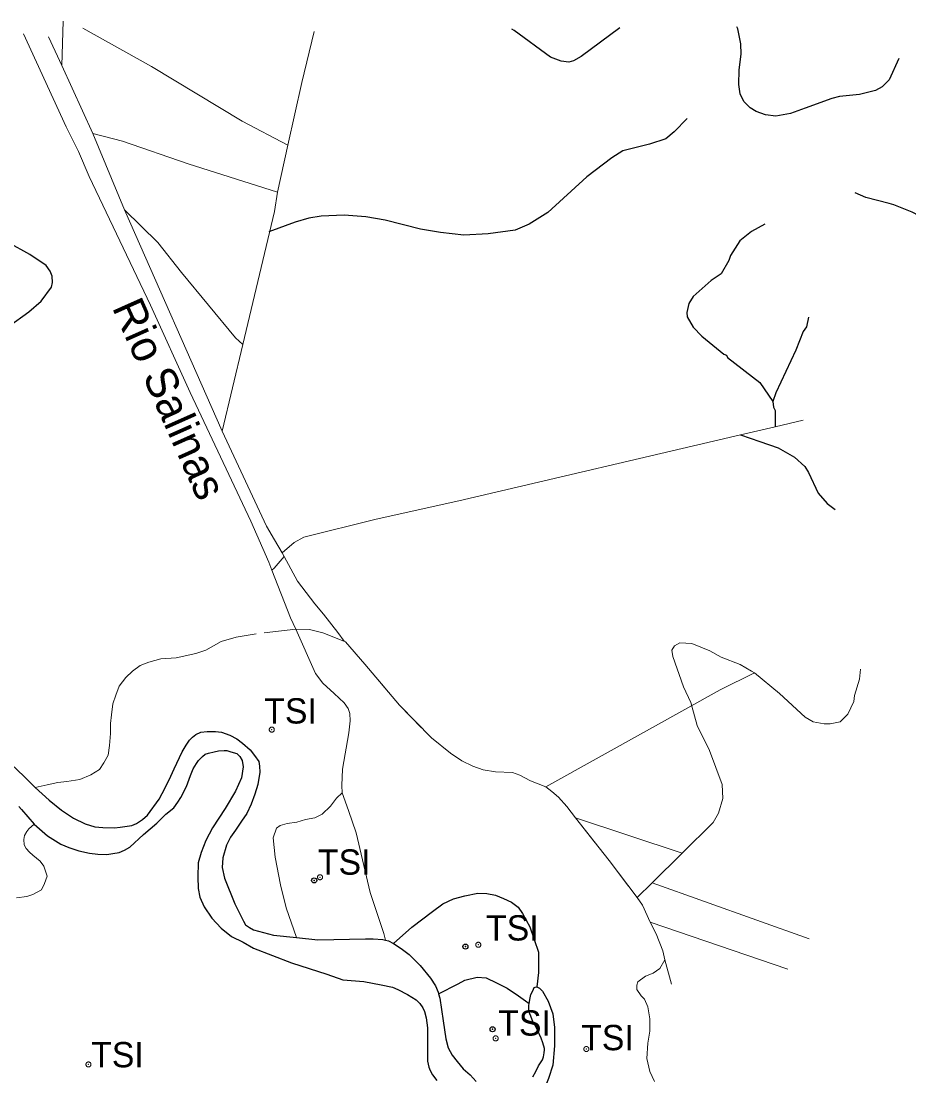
# Model space of a CAD drawing. Extents: x 317.8 to 344.1, y 7676.8 to 7704.8.
# Drawn here: x 327.586 to 330.394, y 7701.313 to 7704.649 of the extents above; entities that cross this region are included whole.
import ezdxf
from ezdxf.enums import TextEntityAlignment as Align

# ---------------------------------------------------------------- set-up
doc = ezdxf.new("R2010")
doc.units = 0
doc.header["$LTSCALE"] = 0.032
doc.header["$PDMODE"] = 32
doc.header["$PDSIZE"] = 0.016
doc.linetypes.add('SHORT_DASHED', pattern=[2.7, 1.5, -1.2])
for name, color, linetype, lineweight in [('1', 7, 'Continuous', 13), ('2', 7, 'Continuous', 25), ('21', 7, 'SHORT_DASHED', 13), ('7', 7, 'Continuous', 25)]:
    doc.layers.add(name, color=color, linetype=linetype, lineweight=lineweight)
doc.layers.add('54', color=7, linetype='Continuous')
doc.layers.add('61', color=7, linetype='Continuous')

msp = doc.modelspace()

# ---------------------------------------------------------------- linework, layer by layer
at = {"layer": '1'}
for p, q in [((327.7148, 7704.5089), (327.719, 7704.649)), ((329.9703, 7703.366), (330.0591, 7703.3868)), ((329.8615, 7703.3405), (329.9703, 7703.366)), ((329.3394, 7702.1291), (329.6765, 7702.0179)), ((330.0781, 7701.7465), (329.5817, 7701.9243)), ((330.0113, 7701.6505), (329.5753, 7701.7996)), ((329.6426, 7701.6032), (329.6223, 7701.6809))]:
    msp.add_line(p, q, dxfattribs=at)
for points in [[(327.7813, 7704.6267), (327.9985, 7704.5051), (328.2853, 7704.3327), (328.4293, 7704.2565)], [(328.2224, 7703.3525), (328.2872, 7703.6265), (328.3875, 7704.0467), (328.3974, 7704.1077), (328.4293, 7704.2565), (328.4741, 7704.4547), (328.5131, 7704.6161)], [(328.3696, 7702.9377), (328.3124, 7703.068), (328.1207, 7703.4743), (327.995, 7703.7503), (327.8012, 7704.1573), (327.7672, 7704.2368), (327.7283, 7704.3145), (327.5937, 7704.6082)], [(328.4115, 7702.968), (328.387, 7703.0084), (328.3619, 7703.0522), (328.2224, 7703.3525), (327.9132, 7704.0523), (327.813, 7704.2936), (327.7148, 7704.5089), (327.673, 7704.5988)], [(328.3974, 7704.1077), (328.1141, 7704.1977), (327.9064, 7704.2698), (327.813, 7704.2936)], [(328.2872, 7703.6265), (328.264, 7703.6473), (328.0929, 7703.854), (328.0185, 7703.9485), (327.9132, 7704.0523)], [(328.4115, 7702.968), (328.4494, 7703.0004), (328.4804, 7703.0175), (328.7088, 7703.0743), (328.9707, 7703.1316), (329.8615, 7703.3405)], [(328.4177, 7702.9563), (328.386, 7702.9194), (328.3795, 7702.9123)], [(328.6081, 7702.6882), (328.5875, 7702.7156), (328.5421, 7702.7733), (328.5155, 7702.8059), (328.4602, 7702.8783), (328.4177, 7702.9563), (328.4115, 7702.968)], [(328.3696, 7702.9377), (328.3795, 7702.9123), (328.4384, 7702.7618), (328.4545, 7702.7257)], [(328.4545, 7702.7257), (328.5171, 7702.5857), (328.5406, 7702.5557), (328.5765, 7702.523), (328.6077, 7702.4933), (328.6202, 7702.4753), (328.6257, 7702.4597), (328.6272, 7702.4363), (328.6225, 7702.3981), (328.6022, 7702.2833), (328.6002, 7702.2318), (328.601, 7702.2084)], [(328.6081, 7702.6882), (328.612, 7702.6857), (328.673, 7702.6158), (328.7828, 7702.486), (328.8839, 7702.3825), (328.9438, 7702.3338), (328.98, 7702.3101), (329.015, 7702.2926), (329.0474, 7702.2814), (329.0861, 7702.2751), (329.1398, 7702.2726), (329.1635, 7702.2639), (329.1972, 7702.2464), (329.2458, 7702.2277), (329.2646, 7702.2127), (329.2858, 7702.1952), (329.312, 7702.1653), (329.3394, 7702.1291), (329.4455, 7701.9943), (329.5339, 7701.8771)], [(329.5339, 7701.8771), (329.5817, 7701.9243), (329.6765, 7702.0179), (329.7748, 7702.1149), (329.7913, 7702.1446), (329.8054, 7702.1903), (329.8031, 7702.2351), (329.7634, 7702.3424), (329.7239, 7702.4214), (329.7068, 7702.4827), (329.7036, 7702.4941), (329.6807, 7702.5436), (329.6471, 7702.6394), (329.6442, 7702.6602), (329.6529, 7702.6732), (329.6693, 7702.6826), (329.7068, 7702.6807), (329.7636, 7702.6571), (329.7997, 7702.6374), (329.8597, 7702.614), (329.896, 7702.5931), (329.9052, 7702.5878), (329.9848, 7702.5228), (330.0657, 7702.448), (330.0912, 7702.433), (330.126, 7702.4267), (330.1449, 7702.4267), (330.1766, 7702.4334), (330.2002, 7702.4571), (330.2194, 7702.4972), (330.222, 7702.5168), (330.2375, 7702.5677), (330.2409, 7702.5995)], [(329.2458, 7702.2277), (329.5733, 7702.4099), (329.7968, 7702.5341), (329.9052, 7702.5878)], [(328.601, 7702.2084), (328.5833, 7702.1919), (328.5641, 7702.1663), (328.5385, 7702.1407), (328.5154, 7702.1291), (328.486, 7702.124), (328.4578, 7702.1163), (328.4271, 7702.1112), (328.4053, 7702.1048), (328.3938, 7702.0971), (328.3836, 7702.0664), (328.39, 7702.005), (328.4066, 7701.9179), (328.4245, 7701.845), (328.4572, 7701.7506)], [(328.601, 7702.2084), (328.6213, 7702.153), (328.6455, 7702.082), (328.6904, 7701.8932), (328.7337, 7701.7637), (328.7383, 7701.7425)], [(329.5339, 7701.8771), (329.5516, 7701.8533), (329.5753, 7701.7996), (329.5941, 7701.7622), (329.6153, 7701.7085), (329.6223, 7701.6809), (329.6223, 7701.6809)]]:
    msp.add_lwpolyline(points, dxfattribs=at)
at = {"layer": '2'}
for points in [[(326.9014, 7702.938), (326.886, 7702.8902), (326.8769, 7702.8538), (326.8769, 7702.8162), (326.8838, 7702.7843), (326.8952, 7702.7593), (326.9088, 7702.7342), (326.9441, 7702.6943), (326.9692, 7702.6704), (326.9897, 7702.6556), (327.0443, 7702.6306), (327.1206, 7702.5862), (327.1605, 7702.5611), (327.2846, 7702.4791), (327.4873, 7702.3436), (327.5534, 7702.3003), (327.5955, 7702.2605), (327.6308, 7702.2252)], [(327.6308, 7702.2252), (327.6752, 7702.1853), (327.7139, 7702.1534), (327.7515, 7702.1284), (327.7891, 7702.1102), (327.8198, 7702.101), (327.8449, 7702.0988), (327.8813, 7702.0976), (327.8996, 7702.0999), (327.936, 7702.1056), (327.9508, 7702.1113), (327.9702, 7702.1238), (327.9861, 7702.1375), (328.0225, 7702.1887), (328.0419, 7702.224), (328.0601, 7702.2616), (328.0704, 7702.2844), (328.0954, 7702.3379), (328.1079, 7702.3595), (328.1182, 7702.3755), (328.1284, 7702.3846), (328.1387, 7702.3926), (328.1546, 7702.4005), (328.174, 7702.4028), (328.2013, 7702.4028), (328.2195, 7702.4005), (328.2457, 7702.3914), (328.2685, 7702.3789), (328.2867, 7702.3652), (328.3106, 7702.3447), (328.3243, 7702.3265), (328.338, 7702.3072), (328.3403, 7702.2924), (328.3414, 7702.2741), (328.3346, 7702.2354), (328.3255, 7702.2047), (328.3141, 7702.1728), (328.3004, 7702.1432), (328.2833, 7702.1193), (328.264, 7702.0908), (328.248, 7702.068), (328.2355, 7702.043), (328.2241, 7702.0031), (328.2218, 7701.9724), (328.2298, 7701.9382), (328.2617, 7701.8574), (328.289, 7701.8027), (328.2958, 7701.7913), (328.3084, 7701.7822), (328.3209, 7701.7754), (328.3847, 7701.7583), (328.4572, 7701.7506)], [(327.6279, 7702.1092), (327.67, 7702.0729), (327.7121, 7702.046), (327.7367, 7702.0354), (327.7683, 7702.0249), (327.8023, 7702.0179), (327.8292, 7702.0144), (327.8573, 7702.0132), (327.876, 7702.0167), (327.8959, 7702.0202), (327.9135, 7702.0272), (327.9298, 7702.0366), (327.9732, 7702.0764), (328.0153, 7702.1127), (328.0434, 7702.1408), (328.0691, 7702.1607), (328.082, 7702.1794), (328.0914, 7702.1934), (328.1089, 7702.2286), (328.1218, 7702.2637), (328.13, 7702.2847), (328.1405, 7702.3011), (328.1476, 7702.3105), (328.1593, 7702.3234), (328.1686, 7702.3304), (328.1792, 7702.3339), (328.1967, 7702.3386), (328.2108, 7702.3409), (328.2283, 7702.3421), (328.2365, 7702.3421), (328.2494, 7702.3386), (328.2681, 7702.3327), (328.2775, 7702.3234), (328.2857, 7702.3105), (328.288, 7702.2906), (328.2833, 7702.2555), (328.2646, 7702.2133), (328.2318, 7702.1595), (328.1909, 7702.0975), (328.1698, 7702.0577), (328.1557, 7702.0202), (328.1464, 7701.9874), (328.1452, 7701.943), (328.1464, 7701.9055), (328.1511, 7701.8786), (328.1651, 7701.8481), (328.1897, 7701.8119), (328.219, 7701.7803), (328.2517, 7701.7545), (328.288, 7701.7358), (328.3208, 7701.7171), (328.4413, 7701.6714), (328.5525, 7701.6351), (328.604, 7701.6176), (328.6696, 7701.6117), (328.7246, 7701.6012), (328.7609, 7701.5942), (328.7773, 7701.5871), (328.8077, 7701.5707), (328.8358, 7701.5544), (328.8475, 7701.5427), (328.8569, 7701.5286), (328.8615, 7701.5169), (328.8674, 7701.497), (328.8709, 7701.4654), (328.8709, 7701.4279), (328.8709, 7701.4022), (328.8709, 7701.3776), (328.8709, 7701.3601), (328.8756, 7701.3413), (328.8795, 7701.3303), (328.8867, 7701.317), (328.9013, 7701.2992)], [(327.5785, 7702.1649), (327.5869, 7702.156), (327.6279, 7702.1092)], [(328.4572, 7701.7506), (328.5247, 7701.7435), (328.6751, 7701.7469), (328.699, 7701.7469), (328.7297, 7701.7446), (328.7383, 7701.7425)], [(328.7383, 7701.7425), (328.7479, 7701.7401), (328.7639, 7701.7321)], [(328.7639, 7701.7321), (328.7878, 7701.7161), (328.8128, 7701.6968), (328.8478, 7701.6626), (328.8812, 7701.6228), (328.8971, 7701.5977), (328.9051, 7701.5784), (328.9065, 7701.5734)], [(329.2171, 7701.5954), (329.2251, 7701.5909), (329.2353, 7701.5818), (329.2524, 7701.5499), (329.2672, 7701.51), (329.2729, 7701.4668), (329.2729, 7701.4087), (329.2672, 7701.3472), (329.2536, 7701.305), (329.2137, 7701.2071), (329.1932, 7701.1365), (329.1613, 7701.0352), (329.1476, 7700.968), (329.1385, 7700.9372), (329.1294, 7700.9167), (329.1123, 7700.8917), (329.0679, 7700.8518), (328.9438, 7700.7459), (328.8743, 7700.6867), (328.8459, 7700.6605), (328.8345, 7700.6468), (328.8163, 7700.6218), (328.8117, 7700.607), (328.8106, 7700.5637)], [(329.193, 7701.5426), (329.1955, 7701.5601), (329.1978, 7701.5704), (329.2046, 7701.5829), (329.2091, 7701.5932), (329.2114, 7701.5943), (329.2171, 7701.5954)], [(328.9065, 7701.5734), (328.9108, 7701.559), (328.921, 7701.4872), (328.929, 7701.4303), (328.937, 7701.4018), (328.9495, 7701.3791), (328.9654, 7701.3586), (328.9837, 7701.3358), (329.0064, 7701.3164), (329.0247, 7701.2959)], [(329.2046, 7701.3107), (329.2137, 7701.3278), (329.2228, 7701.3449), (329.2353, 7701.3643), (329.2376, 7701.3734), (329.2399, 7701.3859), (329.241, 7701.3961), (329.241, 7701.3996), (329.2365, 7701.4178), (329.2308, 7701.4326), (329.2194, 7701.4576), (329.2103, 7701.4759), (329.2057, 7701.4827), (329.1978, 7701.5021), (329.1921, 7701.5169), (329.1921, 7701.5362), (329.193, 7701.5426)]]:
    msp.add_lwpolyline(points, dxfattribs=at)
at = {"layer": '21'}
msp.add_line((329.6216, 7701.6797), (329.6214, 7701.6794), dxfattribs=at)
for points in [[(328.4545, 7702.7257), (328.329, 7702.7115), (328.2667, 7702.7011), (328.2183, 7702.6873), (328.1698, 7702.6596), (328.1387, 7702.6492), (328.0764, 7702.6354), (328.028, 7702.6319), (327.9899, 7702.6215), (327.9622, 7702.6111), (327.938, 7702.5938), (327.9172, 7702.5731), (327.8965, 7702.5454), (327.8861, 7702.5177), (327.8757, 7702.49), (327.8722, 7702.4554), (327.8688, 7702.4277), (327.8688, 7702.3966), (327.8653, 7702.3585), (327.8619, 7702.3274), (327.848, 7702.3032), (327.8342, 7702.2824), (327.8065, 7702.2651), (327.7719, 7702.2512), (327.7304, 7702.2443), (327.7027, 7702.2409), (327.6681, 7702.2339), (327.6308, 7702.2252)], [(328.4545, 7702.7257), (328.4986, 7702.7253), (328.5401, 7702.715), (328.6067, 7702.6879)], [(328.6067, 7702.6879), (328.612, 7702.6857), (328.673, 7702.6158), (328.7828, 7702.486), (328.8839, 7702.3825), (328.9438, 7702.3338), (328.98, 7702.3101), (329.015, 7702.2926), (329.0474, 7702.2814), (329.0861, 7702.2751), (329.1398, 7702.2726), (329.1635, 7702.2639), (329.1972, 7702.2464), (329.2458, 7702.2277), (329.2646, 7702.2127), (329.2858, 7702.1952), (329.312, 7702.1653), (329.3394, 7702.1291), (329.4455, 7701.9943), (329.5339, 7701.8771)], [(327.5719, 7701.877), (327.604, 7701.8811), (327.6236, 7701.8867), (327.6501, 7701.9021), (327.6599, 7701.9217), (327.6683, 7701.9454), (327.6585, 7701.9762), (327.6459, 7701.9929), (327.6236, 7702.0111), (327.6124, 7702.0209), (327.6026, 7702.032), (327.5957, 7702.0446), (327.5943, 7702.0614), (327.597, 7702.074), (327.604, 7702.0865), (327.611, 7702.0949), (327.6279, 7702.1092)], [(329.5339, 7701.8771), (329.5516, 7701.8533), (329.5753, 7701.7996), (329.5941, 7701.7622), (329.6153, 7701.7085), (329.6223, 7701.6809), (329.6223, 7701.6809)], [(329.6223, 7701.6809), (329.606, 7701.6526), (329.5852, 7701.6387), (329.561, 7701.6284), (329.5368, 7701.611), (329.5333, 7701.6007), (329.5333, 7701.5868), (329.5471, 7701.5661), (329.5575, 7701.5557), (329.5679, 7701.5315), (329.5748, 7701.4934), (329.5748, 7701.4553), (329.5679, 7701.4173), (329.5644, 7701.3688), (329.5748, 7701.3273), (329.5887, 7701.2961)]]:
    msp.add_lwpolyline(points, dxfattribs=at)
for p in [(328.3789, 7702.4084), (328.5314, 7701.9416), (329.0318, 7701.728), (329.0868, 7701.432), (329.3736, 7701.3984), (327.7991, 7701.3496)]:
    msp.add_point(p, dxfattribs=at)
at = {"layer": '54'}
for p in [(328.5128, 7701.9316), (328.9911, 7701.7224), (329.0771, 7701.4608)]:
    msp.add_point(p, dxfattribs=at)
at = {"layer": '7'}
for points in [[(329.4795, 7704.6274), (329.3573, 7704.5375), (329.333, 7704.5234), (329.3185, 7704.5196), (329.2945, 7704.5222), (329.2607, 7704.5351), (329.1452, 7704.6192), (329.1379, 7704.6239)], [(330.3615, 7704.5311), (330.3316, 7704.4632), (330.309, 7704.4412), (330.2876, 7704.4298), (330.2374, 7704.4171), (330.1746, 7704.4104), (330.1498, 7704.4047), (330.0656, 7704.3737), (330.0191, 7704.3565), (329.9728, 7704.3485), (329.9405, 7704.3526), (329.9103, 7704.363), (329.8917, 7704.3749), (329.8713, 7704.3944), (329.8596, 7704.4187), (329.856, 7704.4481), (329.8569, 7704.4951), (329.8634, 7704.5449), (329.8626, 7704.5774), (329.853, 7704.6249), (329.8499, 7704.6311)], [(329.6923, 7704.3412), (329.6513, 7704.2985), (329.6249, 7704.2769), (329.5735, 7704.2595), (329.4893, 7704.2384), (329.454, 7704.2163), (329.3752, 7704.1561), (329.2516, 7704.0441), (329.1933, 7704.0072), (329.1489, 7703.9874), (329.0633, 7703.976), (328.9862, 7703.9719), (328.912, 7703.9801), (328.849, 7703.9909), (328.7379, 7704.0191), (328.6766, 7704.0304), (328.6077, 7704.0355), (328.5355, 7704.0322), (328.4963, 7704.0256), (328.4523, 7704.0133), (328.3691, 7703.9826)], [(330.677, 7704.0232), (330.6314, 7704.0281), (330.5451, 7704.0175), (330.4685, 7704.0209), (330.4266, 7704.0327), (330.4041, 7704.0451), (330.3461, 7704.0683), (330.3313, 7704.0722), (330.2577, 7704.0916), (330.2237, 7704.1056)], [(329.9385, 7704.007), (329.8961, 7703.9839), (329.8588, 7703.9542), (329.8292, 7703.9075), (329.8239, 7703.8923), (329.7998, 7703.8499), (329.7685, 7703.8288), (329.7118, 7703.7779), (329.6979, 7703.756), (329.6915, 7703.7272), (329.6929, 7703.7137), (329.7116, 7703.6813), (329.7385, 7703.6526), (329.8088, 7703.5956), (329.817, 7703.5925), (329.8203, 7703.5848), (329.9223, 7703.5063), (329.9634, 7703.4461)], [(327.5466, 7703.6835), (327.6102, 7703.7295), (327.6493, 7703.7635), (327.6824, 7703.8073), (327.6857, 7703.8228), (327.6848, 7703.8423), (327.6783, 7703.8586), (327.6653, 7703.8756), (327.6142, 7703.9111), (327.5447, 7703.9491)], [(330.0762, 7703.7128), (330.0696, 7703.6821), (330.0597, 7703.6675), (330.0358, 7703.6084), (329.9728, 7703.473), (329.9634, 7703.4461)], [(329.9634, 7703.4461), (329.9655, 7703.428), (329.9703, 7703.4178), (329.9703, 7703.366)], [(329.8615, 7703.3405), (329.9223, 7703.3199), (329.9807, 7703.2992), (330.0319, 7703.2703), (330.0642, 7703.2402), (330.0761, 7703.2213), (330.1063, 7703.1561), (330.1356, 7703.1234), (330.1602, 7703.104)], [(328.7639, 7701.7321), (328.8217, 7701.7838), (328.8874, 7701.8331), (328.9203, 7701.857), (328.9532, 7701.8734), (328.989, 7701.8824), (329.0309, 7701.8914), (329.0593, 7701.8899), (329.0862, 7701.8854), (329.1116, 7701.8749), (329.137, 7701.863), (329.1579, 7701.8465), (329.1713, 7701.8271), (329.1953, 7701.7853), (329.2222, 7701.7046), (329.2222, 7701.6403), (329.2171, 7701.5954)], [(328.9065, 7701.5734), (328.9681, 7701.6044), (328.989, 7701.6164), (329.0279, 7701.6254), (329.0563, 7701.6239), (329.0892, 7701.6074), (329.1235, 7701.591), (329.1594, 7701.5671), (329.1808, 7701.5513), (329.193, 7701.5426)]]:
    msp.add_lwpolyline(points, dxfattribs=at)

# ---------------------------------------------------------------- texts
at = {"layer": '61'}
msp.add_text('Rio Salinas', height=0.1, rotation=294.02, dxfattribs=at).set_placement((328.0102, 7703.4349), align=Align.CENTER)
for p in [(328.355, 7702.4277), (328.5246, 7701.9497), (329.0565, 7701.7415), (329.0951, 7701.4409), (329.3572, 7701.3946), (327.8076, 7701.3406)]:
    msp.add_text('TSI', height=0.08, dxfattribs=at).set_placement(p)

doc.saveas('drawing.dxf')
